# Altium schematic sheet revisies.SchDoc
size A3; ApprovedBy: CdB; CheckedBy: CdB; DrawnBy: RT; Engineer: CdB; Organization: Faber Electronics B.V.; Address1: Th. Dobbeweg 1,; Address2: 6883 GN Velp,; Address3: Netherlands; Address4: T: 026-38 46 800; DocumentNumber: 6; Revision: 2.1.3; SheetNumber: 6; SheetTotal: 6; Status: Final
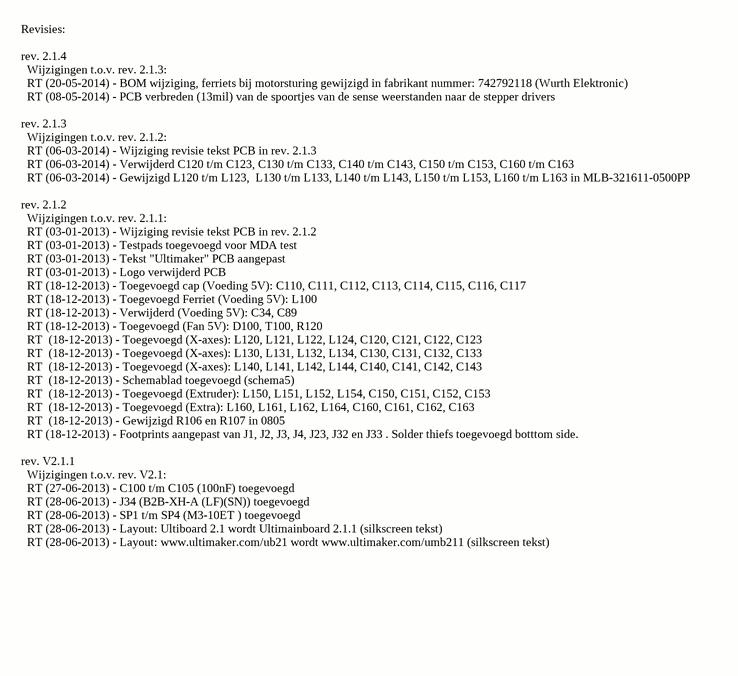
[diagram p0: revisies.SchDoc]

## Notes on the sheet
- Revisies:
  rev. 2.1.4
  Wijzigingen t.o.v. rev. 2.1.3:
  RT (20-05-2014) - BOM wijziging, ferriets bij motorsturing gewijzigd in fabrikant nummer: 742792118 (Wurth Elektronic)
  RT (08-05-2014) - PCB verbreden (13mil) van de spoortjes van de sense weerstanden naar de stepper drivers
  rev. 2.1.3
  Wijzigingen t.o.v. rev. 2.1.2:
  RT (06-03-2014) - Wijziging revisie tekst PCB in rev. 2.1.3
  RT (06-03-2014) - Verwijderd C120 t/m C123, C130 t/m C133, C140 t/m C143, C150 t/m C153, C160 t/m C163
  RT (06-03-2014) - Gewijzigd L120 t/m L123,  L130 t/m L133, L140 t/m L143, L150 t/m L153, L160 t/m L163 in MLB-321611-0500PP
  rev. 2.1.2
  Wijzigingen t.o.v. rev. 2.1.1:
  RT (03-01-2013) - Wijziging revisie tekst PCB in rev. 2.1.2
  RT (03-01-2013) - Testpads toegevoegd voor MDA test
  RT (03-01-2013) - Tekst "Ultimaker" PCB aangepast
  RT (03-01-2013) - Logo verwijderd PCB
  RT (18-12-2013) - Toegevoegd cap (Voeding 5V): C110, C111, C112, C113, C114, C115, C116, C117
  RT (18-12-2013) - Toegevoegd Ferriet (Voeding 5V): L100
  RT (18-12-2013) - Verwijderd (Voeding 5V): C34, C89
  RT (18-12-2013) - Toegevoegd (Fan 5V): D100, T100, R120
  RT  (18-12-2013) - Toegevoegd (X-axes): L120, L121, L122, L124, C120, C121, C122, C123
  RT  (18-12-2013) - Toegevoegd (X-axes): L130, L131, L132, L134, C130, C131, C132, C133
  RT  (18-12-2013) - Toegevoegd (X-axes): L140, L141, L142, L144, C140, C141, C142, C143
  RT  (18-12-2013) - Schemablad toegevoegd (schema5)
  RT  (18-12-2013) - Toegevoegd (Extruder): L150, L151, L152, L154, C150, C151, C152, C153
  RT  (18-12-2013) - Toegevoegd (Extra): L160, L161, L162, L164, C160, C161, C162, C163
  RT  (18-12-2013) - Gewijzigd R106 en R107 in 0805
  RT (18-12-2013) - Footprints aangepast van J1, J2, J3, J4, J23, J32 en J33 . Solder thiefs toegevoegd botttom side.
  rev. V2.1.1
  Wijzigingen t.o.v. rev. V2.1:
  RT (27-06-2013) - C100 t/m C105 (100nF) toegevoegd
  RT (28-06-2013) - J34 (B2B-XH-A (LF)(SN)) toegevoegd
  RT (28-06-2013) - SP1 t/m SP4 (M3-10ET ) toegevoegd
  RT (28-06-2013) - Layout: Ultiboard 2.1 wordt Ultimainboard 2.1.1 (silkscreen tekst)
  RT (28-06-2013) - Layout: www.ultimaker.com/ub21 wordt www.ultimaker.com/umb211 (silkscreen tekst)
